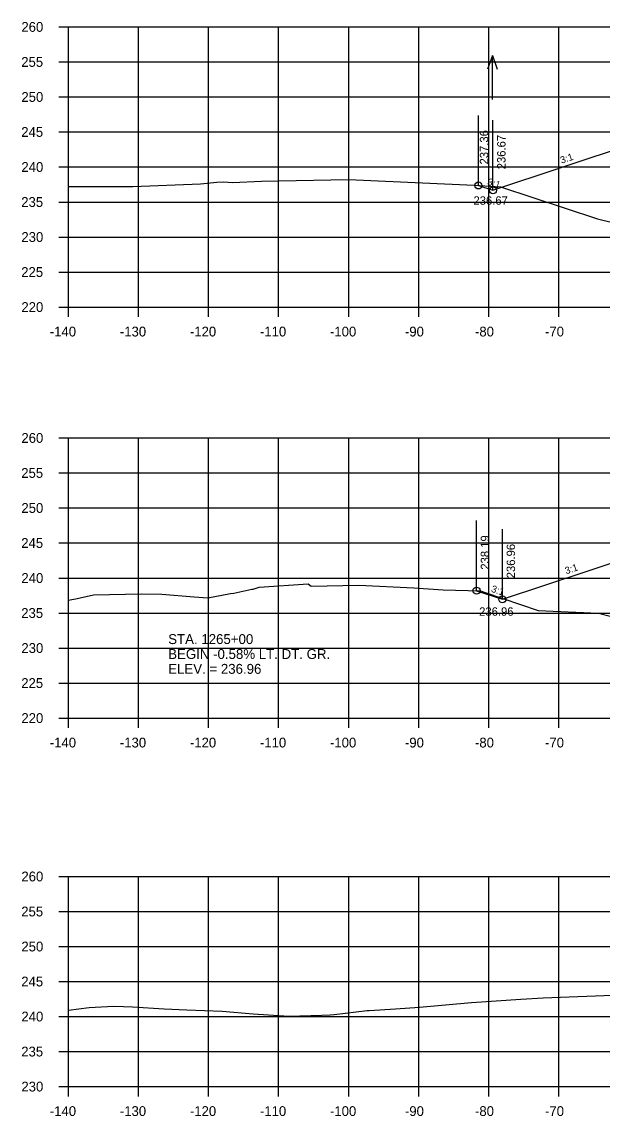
# Model space of a CAD drawing. Extents: x 1342547 to 1344156, y -1532351 to -1517216.
# Drawn here: x 1342556.2 to 1342639, y -1525081.9 to -1524925.6 of the extents above; entities that cross this region are included whole.
import ezdxf

# ---------------------------------------------------------------- set-up
doc = ezdxf.new("R2010")
doc.units = 0
for name, color, linetype in [('R_Axis', 7, 'Continuous'), ('R_Axis Annot', 7, 'Continuous'), ('R_Exist Surface', 7, 'Continuous'), ('R_Fin Surface', 7, 'Continuous'), ('R_Grid', 7, 'Continuous'), ('R_No Plot', 7, 'Continuous'), ('R_Water', 7, 'Continuous'), ('R_Water Annot', 7, 'Continuous'), ('R_Xsect Elev', 7, 'Continuous'), ('R_Xsect Slope', 7, 'Continuous')]:
    doc.layers.add(name, color=color, linetype=linetype)

msp = doc.modelspace()

# ---------------------------------------------------------------- linework, layer by layer
at = {"layer": 'R_Axis'}
for p, q in [((1342561.47, -1524926.35), (1342562.87, -1524926.35)), ((1342562.87, -1524966.35), (1342562.87, -1524926.35)), ((1342561.47, -1524931.35), (1342562.87, -1524931.35)), ((1342561.47, -1524936.35), (1342562.87, -1524936.35)), ((1342561.47, -1524941.35), (1342562.87, -1524941.35)), ((1342561.47, -1524946.35), (1342562.87, -1524946.35)), ((1342561.47, -1524951.35), (1342562.87, -1524951.35)), ((1342561.47, -1524956.35), (1342562.87, -1524956.35)), ((1342561.47, -1524961.35), (1342562.87, -1524961.35)), ((1342561.47, -1524966.35), (1342562.87, -1524966.35)), ((1342562.87, -1524966.35), (1342842.87, -1524966.35)), ((1342562.87, -1524967.75), (1342562.87, -1524966.35)), ((1342572.87, -1524967.75), (1342572.87, -1524966.35)), ((1342582.87, -1524967.75), (1342582.87, -1524966.35)), ((1342592.87, -1524967.75), (1342592.87, -1524966.35)), ((1342602.87, -1524967.75), (1342602.87, -1524966.35)), ((1342612.87, -1524967.75), (1342612.87, -1524966.35)), ((1342622.87, -1524967.75), (1342622.87, -1524966.35)), ((1342632.87, -1524967.75), (1342632.87, -1524966.35)), ((1342561.47, -1524985.04), (1342562.87, -1524985.04)), ((1342562.87, -1525025.04), (1342562.87, -1524985.04)), ((1342561.47, -1524990.04), (1342562.87, -1524990.04)), ((1342561.47, -1524995.04), (1342562.87, -1524995.04)), ((1342561.47, -1525000.04), (1342562.87, -1525000.04)), ((1342561.47, -1525005.04), (1342562.87, -1525005.04)), ((1342561.47, -1525010.04), (1342562.87, -1525010.04)), ((1342561.47, -1525015.04), (1342562.87, -1525015.04)), ((1342561.47, -1525020.04), (1342562.87, -1525020.04)), ((1342561.47, -1525025.04), (1342562.87, -1525025.04)), ((1342562.87, -1525025.04), (1342842.87, -1525025.04)), ((1342562.87, -1525026.44), (1342562.87, -1525025.04)), ((1342572.87, -1525026.44), (1342572.87, -1525025.04)), ((1342582.87, -1525026.44), (1342582.87, -1525025.04)), ((1342592.87, -1525026.44), (1342592.87, -1525025.04)), ((1342602.87, -1525026.44), (1342602.87, -1525025.04)), ((1342612.87, -1525026.44), (1342612.87, -1525025.04)), ((1342622.87, -1525026.44), (1342622.87, -1525025.04)), ((1342632.87, -1525026.44), (1342632.87, -1525025.04)), ((1342561.47, -1525047.66), (1342562.87, -1525047.66)), ((1342562.87, -1525077.66), (1342562.87, -1525047.66)), ((1342561.47, -1525052.66), (1342562.87, -1525052.66)), ((1342561.47, -1525057.66), (1342562.87, -1525057.66)), ((1342561.47, -1525062.66), (1342562.87, -1525062.66)), ((1342561.47, -1525067.66), (1342562.87, -1525067.66)), ((1342561.47, -1525072.66), (1342562.87, -1525072.66)), ((1342561.47, -1525077.66), (1342562.87, -1525077.66)), ((1342562.87, -1525077.66), (1342842.87, -1525077.66)), ((1342562.87, -1525079.06), (1342562.87, -1525077.66)), ((1342572.87, -1525079.06), (1342572.87, -1525077.66)), ((1342582.87, -1525079.06), (1342582.87, -1525077.66)), ((1342592.87, -1525079.06), (1342592.87, -1525077.66)), ((1342602.87, -1525079.06), (1342602.87, -1525077.66)), ((1342612.87, -1525079.06), (1342612.87, -1525077.66)), ((1342622.87, -1525079.06), (1342622.87, -1525077.66)), ((1342632.87, -1525079.06), (1342632.87, -1525077.66))]:
    msp.add_line(p, q, dxfattribs=at)
at = {"layer": 'R_Exist Surface'}
for points in [[(1342562.87, -1524949.14), (1342571.9, -1524949.14), (1342572.04, -1524949.14), (1342581.73, -1524948.77), (1342584.06, -1524948.53), (1342585.03, -1524948.45), (1342586.27, -1524948.55), (1342590.41, -1524948.37), (1342602.81, -1524948.14), (1342604.96, -1524948.21), (1342620.79, -1524948.96), (1342624.56, -1524949.16), (1342638.4, -1524953.74), (1342642.65, -1524954.82)], [(1342562.87, -1525008.2), (1342564.08, -1525007.98), (1342566.45, -1525007.42), (1342573.28, -1525007.32), (1342576.2, -1525007.35), (1342580.81, -1525007.72), (1342582.77, -1525007.87), (1342585.99, -1525007.26), (1342586.45, -1525007.19), (1342589.04, -1525006.63), (1342589.22, -1525006.63), (1342590.07, -1525006.36), (1342597.07, -1525005.85), (1342597.5, -1525006.2), (1342604.33, -1525006.08), (1342612.19, -1525006.44), (1342616.35, -1525006.72), (1342621.7, -1525006.86), (1342622.36, -1525007.12), (1342629.94, -1525009.69), (1342638.53, -1525010.07), (1342642.05, -1525010.97)], [(1342562.87, -1525066.73), (1342565.8, -1525066.37), (1342569.29, -1525066.17), (1342570.73, -1525066.24), (1342572.01, -1525066.29), (1342576.54, -1525066.57), (1342579.77, -1525066.7), (1342584.81, -1525066.91), (1342589.25, -1525067.25), (1342594.32, -1525067.62), (1342599.03, -1525067.46), (1342600.2, -1525067.43), (1342600.81, -1525067.35), (1342605.49, -1525066.81), (1342605.8, -1525066.79), (1342609.57, -1525066.58), (1342612.98, -1525066.34), (1342620.42, -1525065.64), (1342627.46, -1525065.18), (1342630.63, -1525064.99), (1342641.81, -1525064.58)]]:
    msp.add_lwpolyline(points, dxfattribs=at)
at = {"layer": 'R_Fin Surface'}
for points in [[(1342621.39, -1524948.99), (1342623.46, -1524949.68), (1342643.37, -1524943.05), (1342657.09, -1524940.76), (1342665.37, -1524939.38), (1342671.37, -1524939.14), (1342673.37, -1524939.1), (1342702.87, -1524938.51), (1342732.37, -1524939.1), (1342734.37, -1524939.14), (1342740.37, -1524939.38), (1342748.64, -1524940.76), (1342762.37, -1524943.05), (1342763.75, -1524943.51), (1342767.83, -1524942.15)], [(1342621.12, -1525006.85), (1342624.82, -1525008.08), (1342643.37, -1525001.9), (1342657.09, -1524999.61), (1342665.37, -1524998.23), (1342671.37, -1524997.99), (1342673.37, -1524997.95), (1342702.87, -1524997.36), (1342734.37, -1524997.99)]]:
    msp.add_lwpolyline(points, dxfattribs=at)
at = {"layer": 'R_Grid'}
for p, q in [((1342562.87, -1524926.35), (1342842.87, -1524926.35)), ((1342562.87, -1524966.35), (1342562.87, -1524926.35)), ((1342572.87, -1524966.35), (1342572.87, -1524926.35)), ((1342582.87, -1524966.35), (1342582.87, -1524926.35)), ((1342592.87, -1524966.35), (1342592.87, -1524926.35)), ((1342602.87, -1524966.35), (1342602.87, -1524926.35)), ((1342612.87, -1524966.35), (1342612.87, -1524926.35)), ((1342622.87, -1524966.35), (1342622.87, -1524926.35)), ((1342632.87, -1524966.35), (1342632.87, -1524926.35)), ((1342562.87, -1524931.35), (1342842.87, -1524931.35)), ((1342562.87, -1524936.35), (1342842.87, -1524936.35)), ((1342562.87, -1524941.35), (1342842.87, -1524941.35)), ((1342562.87, -1524946.35), (1342842.87, -1524946.35)), ((1342562.87, -1524951.35), (1342842.87, -1524951.35)), ((1342562.87, -1524956.35), (1342842.87, -1524956.35)), ((1342562.87, -1524961.35), (1342842.87, -1524961.35)), ((1342562.87, -1524966.35), (1342842.87, -1524966.35)), ((1342562.87, -1524985.04), (1342842.87, -1524985.04)), ((1342562.87, -1525025.04), (1342562.87, -1524985.04)), ((1342572.87, -1525025.04), (1342572.87, -1524985.04)), ((1342582.87, -1525025.04), (1342582.87, -1524985.04)), ((1342592.87, -1525025.04), (1342592.87, -1524985.04)), ((1342602.87, -1525025.04), (1342602.87, -1524985.04)), ((1342612.87, -1525025.04), (1342612.87, -1524985.04)), ((1342622.87, -1525025.04), (1342622.87, -1524985.04)), ((1342632.87, -1525025.04), (1342632.87, -1524985.04)), ((1342562.87, -1524990.04), (1342842.87, -1524990.04)), ((1342562.87, -1524995.04), (1342842.87, -1524995.04)), ((1342562.87, -1525000.04), (1342842.87, -1525000.04)), ((1342562.87, -1525005.04), (1342842.87, -1525005.04)), ((1342562.87, -1525010.04), (1342842.87, -1525010.04)), ((1342562.87, -1525015.04), (1342842.87, -1525015.04)), ((1342562.87, -1525020.04), (1342842.87, -1525020.04)), ((1342562.87, -1525025.04), (1342842.87, -1525025.04)), ((1342562.87, -1525047.66), (1342842.87, -1525047.66)), ((1342562.87, -1525077.66), (1342562.87, -1525047.66)), ((1342572.87, -1525077.66), (1342572.87, -1525047.66)), ((1342582.87, -1525077.66), (1342582.87, -1525047.66)), ((1342592.87, -1525077.66), (1342592.87, -1525047.66)), ((1342602.87, -1525077.66), (1342602.87, -1525047.66)), ((1342612.87, -1525077.66), (1342612.87, -1525047.66)), ((1342622.87, -1525077.66), (1342622.87, -1525047.66)), ((1342632.87, -1525077.66), (1342632.87, -1525047.66)), ((1342562.87, -1525052.66), (1342842.87, -1525052.66)), ((1342562.87, -1525057.66), (1342842.87, -1525057.66)), ((1342562.87, -1525062.66), (1342842.87, -1525062.66)), ((1342562.87, -1525067.66), (1342842.87, -1525067.66)), ((1342562.87, -1525072.66), (1342842.87, -1525072.66)), ((1342562.87, -1525077.66), (1342842.87, -1525077.66))]:
    msp.add_line(p, q, dxfattribs=at)
at = {"layer": 'R_No Plot'}
for centre in [(1342621.39, -1524948.99), (1342623.46, -1524949.68), (1342621.12, -1525006.85), (1342624.82, -1525008.08)]:
    msp.add_circle(centre, 0.5, dxfattribs=at)
at = {"layer": 'R_Water'}
for p, q in [((1342623.38, -1524930.45), (1342622.68, -1524932.37)), ((1342623.38, -1524936.73), (1342623.38, -1524930.45)), ((1342623.38, -1524930.45), (1342624.08, -1524932.37))]:
    msp.add_line(p, q, dxfattribs=at)
at = {"layer": 'R_Xsect Elev'}
for p, q in [((1342621.39, -1524948.99), (1342621.39, -1524938.99)), ((1342623.46, -1524949.68), (1342623.46, -1524939.68)), ((1342621.12, -1525006.85), (1342621.12, -1524996.85)), ((1342624.82, -1525008.08), (1342624.82, -1524998.08))]:
    msp.add_line(p, q, dxfattribs=at)

# ---------------------------------------------------------------- texts
at = {"layer": 'R_Axis Annot'}
for s, p in [('260', (1342556.14, -1524927.05)), ('255', (1342556.12, -1524932.05)), ('250', (1342556.14, -1524937.05)), ('245', (1342556.12, -1524942.05)), ('240', (1342556.14, -1524947.05)), ('235', (1342556.12, -1524952.05)), ('230', (1342556.14, -1524957.05)), ('225', (1342556.12, -1524962.05)), ('220', (1342556.14, -1524967.05)), ('-140', (1342560.2, -1524970.55)), ('-130', (1342570.2, -1524970.55)), ('-120', (1342580.2, -1524970.55)), ('-110', (1342590.2, -1524970.55)), ('-100', (1342600.2, -1524970.55)), ('-90', (1342610.9, -1524970.55)), ('-80', (1342620.9, -1524970.55)), ('-70', (1342630.9, -1524970.55)), ('260', (1342556.14, -1524985.74)), ('255', (1342556.12, -1524990.74)), ('250', (1342556.14, -1524995.74)), ('245', (1342556.12, -1525000.74)), ('240', (1342556.14, -1525005.74)), ('235', (1342556.12, -1525010.74)), ('230', (1342556.14, -1525015.74)), ('225', (1342556.12, -1525020.74)), ('220', (1342556.14, -1525025.74)), ('-140', (1342560.2, -1525029.24)), ('-130', (1342570.2, -1525029.24)), ('-120', (1342580.2, -1525029.24)), ('-110', (1342590.2, -1525029.24)), ('-100', (1342600.2, -1525029.24)), ('-90', (1342610.9, -1525029.24)), ('-80', (1342620.9, -1525029.24)), ('-70', (1342630.9, -1525029.24)), ('260', (1342556.14, -1525048.36)), ('255', (1342556.12, -1525053.36)), ('250', (1342556.14, -1525058.36)), ('245', (1342556.12, -1525063.36)), ('240', (1342556.14, -1525068.36)), ('235', (1342556.12, -1525073.36)), ('230', (1342556.14, -1525078.36)), ('-140', (1342560.2, -1525081.86)), ('-130', (1342570.2, -1525081.86)), ('-120', (1342580.2, -1525081.86)), ('-110', (1342590.2, -1525081.86)), ('-100', (1342600.2, -1525081.86)), ('-90', (1342610.9, -1525081.86)), ('-80', (1342620.9, -1525081.86)), ('-70', (1342630.9, -1525081.86))]:
    msp.add_text(s, height=1.4, dxfattribs=at).set_placement(p)
at = {"layer": 'R_Water Annot'}
for s, height, p in [('236.96', 1.2, (1342621.49, -1525010.43)), ('236.96', 1.2, (1342621.49, -1525010.43)), ('STA. 1265+00', 1.4147, (1342577.1, -1525014.47)), ('BEGIN -0.58% LT. DT. GR.', 1.4147, (1342577.1, -1525016.6)), ('ELEV. = 236.96', 1.4147, (1342577.1, -1525018.72))]:
    msp.add_text(s, height=height, dxfattribs=at).set_placement(p)
at = {"layer": 'R_Xsect Elev'}
for s, p in [('237.36', (1342622.79, -1524945.99)), ('236.67', (1342625.26, -1524946.68)), ('238.19', (1342622.92, -1525003.85)), ('236.96', (1342626.62, -1525005.08))]:
    msp.add_text(s, height=1.2, rotation=90, dxfattribs=at).set_placement(p)
msp.add_text('236.67', height=1.2, dxfattribs=at).set_placement((1342620.68, -1524951.74))
at = {"layer": 'R_Xsect Slope'}
for rotation, p in [(18.4349, (1342633.26, -1524945.89)), (341.5651, (1342622.58, -1524948.86)), (18.4349, (1342633.93, -1525004.51)), (341.5651, (1342623.13, -1525006.99))]:
    msp.add_text('3:1', height=1, rotation=rotation, dxfattribs=at).set_placement(p)

doc.saveas('drawing.dxf')
